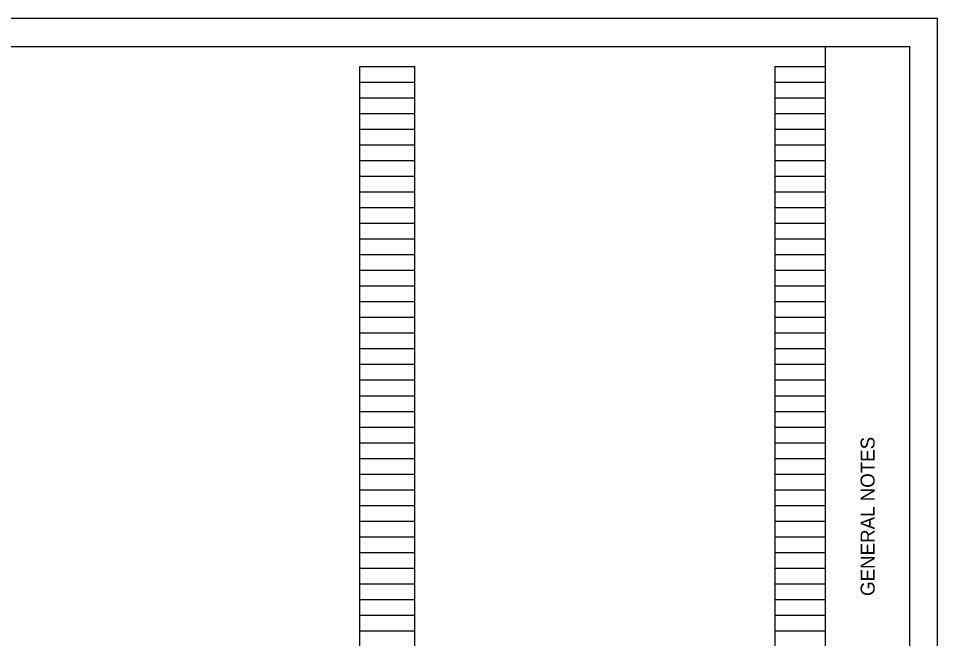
# Model space of a CAD drawing. Extents: x -25 to 34, y -0.5 to 22.
# Drawn here: x 17.58 to 34, y 10.92 to 22 of the extents above; entities that cross this region are included whole.
import ezdxf

# ---------------------------------------------------------------- set-up
doc = ezdxf.new("R2010")
doc.units = 0
for name, color, linetype in [('PV_P_Drive', 7, 'Continuous'), ('SH_Border', 7, 'Continuous'), ('SH_Cut_Line', 7, 'Continuous'), ('SH_Data', 7, 'Continuous')]:
    doc.layers.add(name, color=color, linetype=linetype)

msp = doc.modelspace()

# ---------------------------------------------------------------- linework, layer by layer
at = {"layer": 'PV_P_Drive'}
for p, q in [((23.68, 0.98), (23.68, 21.14)), ((23.68, 21.14), (24.66, 21.14)), ((24.66, 0.98), (24.66, 21.14)), ((31.1, 0.98), (31.1, 21.14)), ((31.1, 21.14), (32, 21.14)), ((32, 0.98), (32, 21.14)), ((23.68, 20.86), (24.66, 20.86)), ((31.1, 20.86), (32, 20.86)), ((23.68, 20.58), (24.66, 20.58)), ((31.1, 20.58), (32, 20.58)), ((23.68, 20.3), (24.66, 20.3)), ((31.1, 20.3), (32, 20.3)), ((23.68, 20.02), (24.66, 20.02)), ((31.1, 20.02), (32, 20.02)), ((23.68, 19.74), (24.66, 19.74)), ((31.1, 19.74), (32, 19.74)), ((23.68, 19.46), (24.66, 19.46)), ((31.1, 19.46), (32, 19.46)), ((23.68, 19.18), (24.66, 19.18)), ((31.1, 19.18), (32, 19.18)), ((23.68, 18.9), (24.66, 18.9)), ((31.1, 18.9), (32, 18.9)), ((23.68, 18.62), (24.66, 18.62)), ((31.1, 18.62), (32, 18.62)), ((23.68, 18.34), (24.66, 18.34)), ((31.1, 18.34), (32, 18.34)), ((23.68, 18.06), (24.66, 18.06)), ((31.1, 18.06), (32, 18.06)), ((23.68, 17.78), (24.66, 17.78)), ((31.1, 17.78), (32, 17.78)), ((23.68, 17.5), (24.66, 17.5)), ((31.1, 17.5), (32, 17.5)), ((23.68, 17.22), (24.66, 17.22)), ((31.1, 17.22), (32, 17.22)), ((23.68, 16.94), (24.66, 16.94)), ((31.1, 16.94), (32, 16.94)), ((23.68, 16.66), (24.66, 16.66)), ((31.1, 16.66), (32, 16.66)), ((23.68, 16.38), (24.66, 16.38)), ((31.1, 16.38), (32, 16.38)), ((23.68, 16.1), (24.66, 16.1)), ((31.1, 16.1), (32, 16.1)), ((23.68, 15.82), (24.66, 15.82)), ((31.1, 15.82), (32, 15.82)), ((23.68, 15.54), (24.66, 15.54)), ((31.1, 15.54), (32, 15.54)), ((23.68, 15.26), (24.66, 15.26)), ((31.1, 15.26), (32, 15.26)), ((23.68, 14.98), (24.66, 14.98)), ((31.1, 14.98), (32, 14.98)), ((23.68, 14.7), (24.66, 14.7)), ((31.1, 14.7), (32, 14.7)), ((23.68, 14.42), (24.66, 14.42)), ((31.1, 14.42), (32, 14.42)), ((23.68, 14.14), (24.66, 14.14)), ((31.1, 14.14), (32, 14.14)), ((23.68, 13.86), (24.66, 13.86)), ((31.1, 13.86), (32, 13.86)), ((23.68, 13.58), (24.66, 13.58)), ((31.1, 13.58), (32, 13.58)), ((23.68, 13.3), (24.66, 13.3)), ((31.1, 13.3), (32, 13.3)), ((23.68, 13.02), (24.66, 13.02)), ((31.1, 13.02), (32, 13.02)), ((23.68, 12.74), (24.66, 12.74)), ((31.1, 12.74), (32, 12.74)), ((23.68, 12.46), (24.66, 12.46)), ((31.1, 12.46), (32, 12.46)), ((23.68, 12.18), (24.66, 12.18)), ((31.1, 12.18), (32, 12.18)), ((23.68, 11.9), (24.66, 11.9)), ((31.1, 11.9), (32, 11.9)), ((23.68, 11.62), (24.66, 11.62)), ((31.1, 11.62), (32, 11.62)), ((23.68, 11.34), (24.66, 11.34)), ((31.1, 11.34), (32, 11.34)), ((23.68, 11.06), (24.66, 11.06)), ((31.1, 11.06), (32, 11.06))]:
    msp.add_line(p, q, dxfattribs=at)
at = {"layer": 'SH_Border'}
msp.add_lwpolyline([(0, 0), (34, 0), (34, 22), (0, 22)], close=True, dxfattribs=at)
at = {"layer": 'SH_Cut_Line'}
msp.add_line((32, 0.5), (32, 21.5), dxfattribs=at)
msp.add_lwpolyline([(1.5, 21.5), (33.5, 21.5), (33.5, 0.5), (1.5, 0.5)], close=True, dxfattribs=at)

# ---------------------------------------------------------------- texts
at = {"layer": 'SH_Data'}
msp.add_text('GENERAL NOTES', height=0.25, rotation=90, dxfattribs=at).set_placement((32.875, 11.682))

doc.saveas('drawing.dxf')
